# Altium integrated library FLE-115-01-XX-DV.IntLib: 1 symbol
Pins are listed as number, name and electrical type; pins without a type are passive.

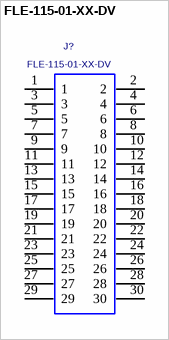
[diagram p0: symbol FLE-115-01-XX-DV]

## FLE-115-01-XX-DV
designator J?
DUAL ROW 0.050'' STRIP ASSEMBLY; MANUFACTURER: SAMTEC
footprint FLE-115-01-XX-DV
pins: 1, 2, 3, 4, 5, 6, 7, 8, 9, 10, 11, 12, 13, 14, 15, 16, 17, 18, 19, 20, 21, 22, 23, 24, 25, 26, 27, 28, 29, 30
